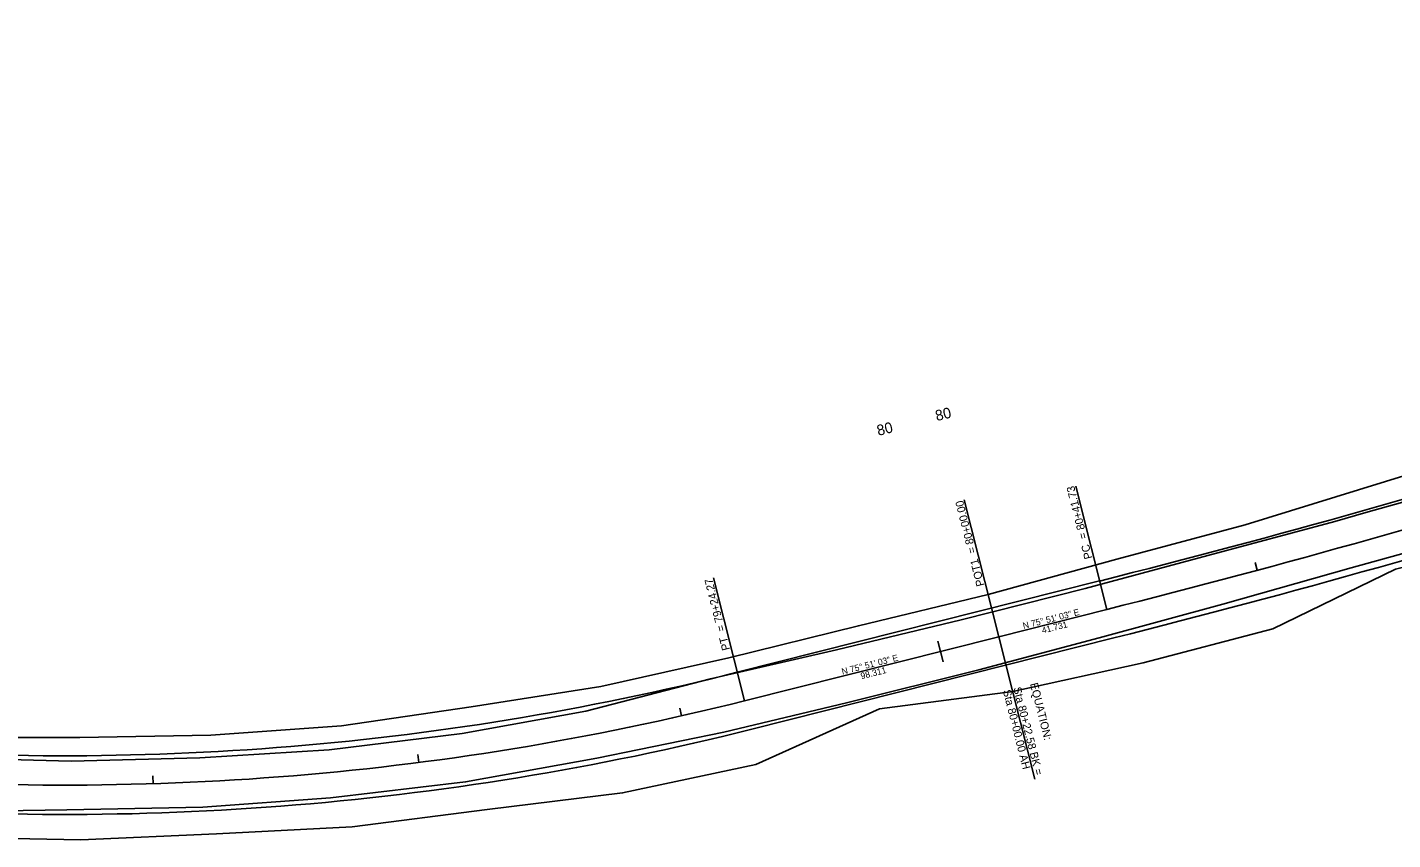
# Model space of a CAD drawing. Extents: x 1965724 to 1970316, y 1117080 to 1118173.
# Drawn here: x 1969309 to 1969821, y 1117865 to 1118169 of the extents above; entities that cross this region are included whole.
import ezdxf

# ---------------------------------------------------------------- set-up
doc = ezdxf.new("R2010")
doc.units = 0
for name, color, linetype in [('RD_EX_Road', 7, 'Continuous'), ('RD_EX_RW', 7, 'Continuous'), ('RD_HC_CL', 7, 'Continuous'), ('RD_HC_Data', 7, 'Continuous'), ('RD_HC_TX_Sta20', 7, 'Continuous'), ('RD_PD_Final_TrvlWay', 7, 'Continuous')]:
    doc.layers.add(name, color=color, linetype=linetype)

msp = doc.modelspace()

# ---------------------------------------------------------------- linework, layer by layer
at = {"layer": 'RD_EX_Road'}
for points in [[(1969810.79, 1117987.5), (1969847.01, 1117997.58), (1969895.73, 1118011.88), (1969956.01, 1118031.22)], [(1969282.94, 1117875.42), (1969323.91, 1117876.08), (1969374.87, 1117877.05), (1969422.79, 1117880.61), (1969473.42, 1117886.58), (1969522.56, 1117895.49), (1969570.22, 1117905.24), (1969616.1, 1117916.13), (1969665.76, 1117928.56), (1969710.86, 1117940.59), (1969757.15, 1117953.18), (1969805.29, 1117966.74), (1969852.3, 1117979.83), (1969901.94, 1117994.12), (1969962.32, 1118012.96)], [(1969283.27, 1117895.43), (1969325.58, 1117894.37), (1969373.77, 1117895.58), (1969422.24, 1117898.63), (1969472.08, 1117904.68), (1969518.53, 1117913.09), (1969565.23, 1117925.16), (1969612.39, 1117936.08), (1969659.13, 1117947.26), (1969705.6, 1117959.01), (1969751.61, 1117971.36), (1969799.19, 1117984.19), (1969810.79, 1117987.5)]]:
    msp.add_lwpolyline(points, dxfattribs=at)
at = {"layer": 'RD_EX_RW'}
for points in [[(1969572.11, 1117933.1), (1969620.65, 1117945.09), (1969669.27, 1117956.79), (1969717.46, 1117970), (1969765.52, 1117982.9), (1969860.61, 1118012.25), (1969908.19, 1118026.72), (1969955.86, 1118040.95), (1970003.14, 1118056.43), (1970049.91, 1118073.39), (1970096.65, 1118090.41), (1970143.42, 1118108.08), (1970190.16, 1118125.84), (1970302.63, 1118169.37)], [(1969278.26, 1117865.85), (1969329.18, 1117864.9), (1969380.05, 1117867.15), (1969430.95, 1117869.7), (1969481.52, 1117876.2), (1969532.27, 1117882.45), (1969582.19, 1117893.11), (1969628.5, 1117913.96), (1969678.44, 1117920.38), (1969727.34, 1117931.16), (1969776, 1117943.94), (1969821.95, 1117966.31), (1969870.71, 1117978.39), (1969918.52, 1117993.72), (1969967.17, 1118006.46), (1970013.77, 1118025.42), (1970061.42, 1118041.22), (1970108.95, 1118057.46), (1970155.44, 1118075.9), (1970316.32, 1118133.6)], [(1969279.74, 1117903.18), (1969328.84, 1117903.14), (1969377.92, 1117904.1), (1969426.92, 1117907.58), (1969475.53, 1117914.66), (1969524.08, 1117922.25), (1969572.11, 1117933.1)]]:
    msp.add_lwpolyline(points, dxfattribs=at)
at = {"layer": 'RD_HC_CL'}
for p, q in [((1969673.25, 1117940.98), (1969713.71, 1117951.18)), ((1969577.93, 1117916.95), (1969673.25, 1117940.98))]:
    msp.add_line(p, q, dxfattribs=at)
for centre, radius, start, end in [((1968809.03, 1121539.8), 3700.9, 284.14929, 290.48234), ((1969323.28, 1118927.09), 1041.74, 264.66612, 284.14929)]:
    msp.add_arc(centre, radius, start, end, dxfattribs=at)
at = {"layer": 'RD_HC_Data'}
for p, q in [((1969713.71, 1117951.18), (1969702.07, 1117997.36)), ((1969673.25, 1117940.98), (1969660.31, 1117992.32)), ((1969770.1, 1117965.87), (1969769.32, 1117968.77)), ((1969577.93, 1117916.95), (1969566.3, 1117963.06)), ((1969673.25, 1117940.98), (1969672.27, 1117944.86)), ((1969651.36, 1117935.46), (1969650.38, 1117939.34)), ((1969673.25, 1117940.98), (1969686.72, 1117887.56)), ((1969673.25, 1117940.98), (1969674.23, 1117937.1)), ((1969651.36, 1117935.46), (1969652.33, 1117931.58)), ((1969554.32, 1117911.29), (1969553.66, 1117914.22)), ((1969455.9, 1117893.82), (1969455.52, 1117896.8)), ((1969356.26, 1117885.87), (1969356.16, 1117888.87))]:
    msp.add_line(p, q, dxfattribs=at)
at = {"layer": 'RD_PD_Final_TrvlWay'}
for p, q in [((1969575.24, 1117927.62), (1969711.03, 1117961.85)), ((1969580.62, 1117906.28), (1969716.4, 1117940.51))]:
    msp.add_line(p, q, dxfattribs=at)
for centre, radius, start, end in [((1968809.03, 1121539.8), 3689.9, 284.14929, 290.48234), ((1968809.03, 1121539.8), 3711.9, 284.14929, 290.48234), ((1969323.28, 1118927.09), 1030.74, 264.66612, 284.14929), ((1969323.28, 1118927.09), 1052.74, 264.66612, 284.14929)]:
    msp.add_arc(centre, radius, start, end, dxfattribs=at)

# ---------------------------------------------------------------- texts
at = {"layer": 'RD_HC_Data'}
for s, height, rotation, p in [('PC  = 80+41.73', 3, 104.1493, (1969708.34, 1117970.45)), ('POT1  = 80+00.00', 3, 104.1493, (1969667.88, 1117960.25)), ('PT  = 79+24.27', 3, 104.1493, (1969572.55, 1117936.22)), ('N 75%%d 51\' 03" E', 2.4, 14.1493, (1969682.54, 1117943.84)), ('41.731', 2.4, 14.1493, (1969689.67, 1117942.13)), ('N 75%%d 51\' 03" E', 2.4, 14.1493, (1969614.64, 1117926.72)), ('98.311', 2.4, 14.1493, (1969621.78, 1117925.01)), ('EQUATION:', 3, 284.1493, (1969684.93, 1117923.3)), ('Sta 80+00.00 AH', 3, 284.1493, (1969674.75, 1117920.73)), ('Sta 80+22.58 BK = ', 3, 284.1493, (1969678.63, 1117921.71))]:
    msp.add_text(s, height=height, rotation=rotation, dxfattribs=at).set_placement(p)
at = {"layer": 'RD_HC_TX_Sta20'}
for p in [(1969649.99, 1118021.74), (1969628.09, 1118016.22)]:
    msp.add_text('80', height=4, rotation=14.1493, dxfattribs=at).set_placement(p)

doc.saveas('drawing.dxf')
